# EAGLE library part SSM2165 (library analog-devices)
Microphone Preamplifier with Variable Compression and Noise Gating OBSOLETE Source: http://www.analog.com/static/imported-files/data_sheets_obsolete/564647885SSM2165.pdf
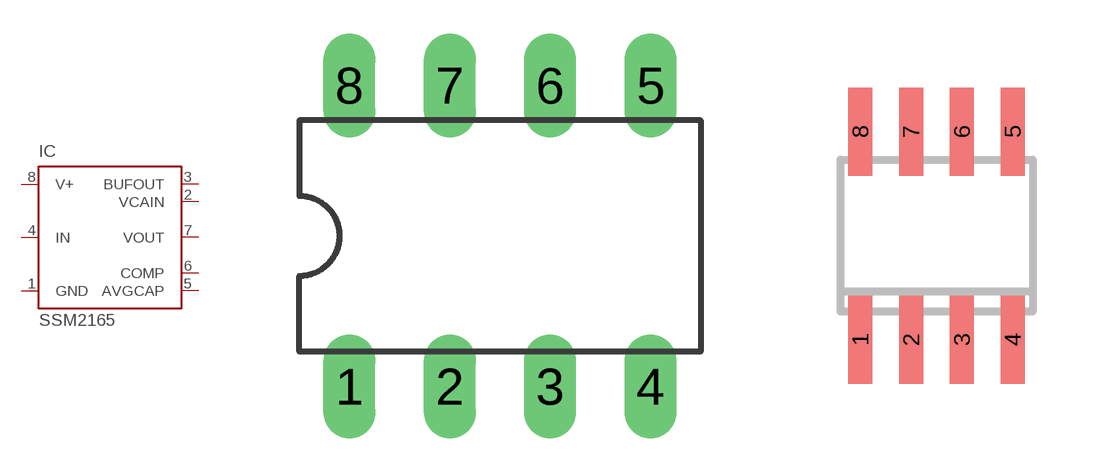
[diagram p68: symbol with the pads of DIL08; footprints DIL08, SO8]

Designator prefix IC

## SSM2165-1P (OC_FARNELL: unknown; OC_NEWARK: unknown), SSM2165-2P (OC_FARNELL: unknown; OC_NEWARK: unknown)  [DIL08]
1  GND  pwr
2  VCAIN  in
3  BUFOUT  out
4  IN  in
5  AVGCAP  pas
6  COMP  pas
7  VOUT  out
8  V+  pwr

## SSM2165-1S (OC_FARNELL: unknown; OC_NEWARK: unknown), SSM2165-2S (OC_FARNELL: unknown; OC_NEWARK: unknown)  [SO8]
Pads as for DIL08

## Footprint DIL08 (pad centres in mm)
Dual In Line Package
drill 0.813 long: 1 -3.81,-3.81; 2 -1.27,-3.81; 3 1.27,-3.81; 4 3.81,-3.81; 5 3.81,3.81; 6 1.27,3.81; 7 -1.27,3.81; 8 -3.81,3.81

## Footprint SO8 (pad centres in mm)
8-Lead Small Outline IC (SO-8) Source: http://www.analog.com/UploadedFiles/Data_Sheets/703465986AD8611_2_0.pdf
smd 0.6 x 2.2: 1 -1.905,-2.6; 2 -0.635,-2.6; 3 0.635,-2.6; 4 1.905,-2.6; 5 1.905,2.6; 6 0.635,2.6; 7 -0.635,2.6; 8 -1.905,2.6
